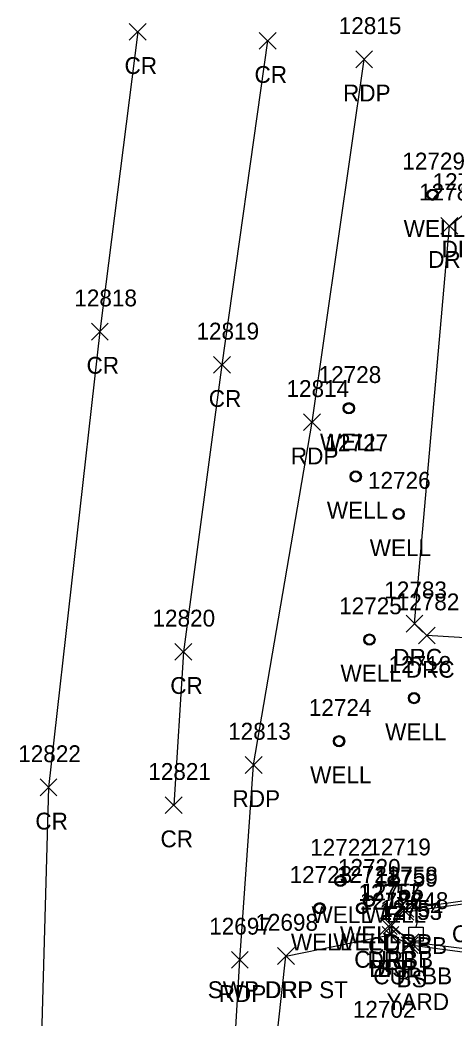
# Model space of a CAD drawing. Extents: x 1769141 to 1770817, y 735471 to 742405.
# Drawn here: x 1770018.6 to 1770070.1, y 741316.5 to 741435 of the extents above; entities that cross this region are included whole.
import ezdxf

# ---------------------------------------------------------------- set-up
doc = ezdxf.new("R2010")
doc.units = 0
for name, color, linetype in [('L_A', 7, 'Continuous'), ('L_I', 7, 'Continuous'), ('L_TIC', 7, 'Continuous'), ('LELB', 7, 'Continuous'), ('P_A', 7, 'Continuous'), ('P_I', 7, 'Continuous'), ('P_TIC', 7, 'Continuous'), ('PET', 7, 'Continuous'), ('PRC', 7, 'Continuous'), ('R_A', 7, 'Continuous'), ('R_I', 7, 'Continuous'), ('R_TIC', 7, 'Continuous'), ('RC', 7, 'Continuous'), ('RDP', 7, 'Continuous'), ('RSW', 7, 'Continuous'), ('U_A', 7, 'Continuous'), ('U_C', 7, 'Continuous'), ('U_I', 7, 'Continuous'), ('ULP', 7, 'Continuous'), ('UWW', 7, 'Continuous')]:
    doc.layers.add(name, color=color, linetype=linetype)

msp = doc.modelspace()

# ---------------------------------------------------------------- linework, layer by layer
at = {"layer": 'L_TIC'}
for points in [[(1770061.58, 741325.38), (1770063.58, 741327.38)], [(1770063.58, 741325.38), (1770061.58, 741327.38)], [(1770063.87, 741324.15), (1770065.87, 741326.15)], [(1770065.87, 741324.15), (1770063.87, 741326.15)]]:
    msp.add_lwpolyline(points, dxfattribs=at)
at = {"layer": 'LELB'}
msp.add_lwpolyline([(1770114.78, 741317.95), (1770086.3, 741322.3), (1770064.87, 741325.15), (1770062.58, 741326.38)], dxfattribs=at)
at = {"layer": 'P_TIC'}
for points in [[(1770031.58, 741432.59), (1770033.58, 741434.59)], [(1770033.58, 741432.59), (1770031.58, 741434.59)], [(1770047, 741431.53), (1770049, 741433.53)], [(1770049, 741431.53), (1770047, 741433.53)], [(1770058.46, 741429.33), (1770060.46, 741431.33)], [(1770060.46, 741429.33), (1770058.46, 741431.33)], [(1770027.07, 741397), (1770029.07, 741399)], [(1770029.07, 741397), (1770027.07, 741399)], [(1770041.58, 741393.06), (1770043.58, 741395.06)], [(1770043.58, 741393.06), (1770041.58, 741395.06)], [(1770052.27, 741386.24), (1770054.27, 741388.24)], [(1770054.27, 741386.24), (1770052.27, 741388.24)], [(1770037, 741358.98), (1770039, 741360.98)], [(1770039, 741358.98), (1770037, 741360.98)], [(1770045.34, 741345.55), (1770047.34, 741347.55)], [(1770047.34, 741345.55), (1770045.34, 741347.55)], [(1770020.98, 741342.88), (1770022.98, 741344.88)], [(1770022.98, 741342.88), (1770020.98, 741344.88)], [(1770035.85, 741340.77), (1770037.85, 741342.77)], [(1770037.85, 741340.77), (1770035.85, 741342.77)], [(1770043.7, 741322.4), (1770045.7, 741324.4)], [(1770045.7, 741322.4), (1770043.7, 741324.4)]]:
    msp.add_lwpolyline(points, dxfattribs=at)
at = {"layer": 'PET'}
msp.add_lwpolyline([(1770060.59, 741195.88), (1770047.65, 741236.89), (1770043.35, 741267.07), (1770042.84, 741291.9), (1770044.7, 741323.4), (1770046.34, 741346.55), (1770053.27, 741387.24), (1770059.46, 741430.33)], dxfattribs=at)
at = {"layer": 'PRC'}
for points in [[(1770032.58, 741433.59), (1770028.07, 741398), (1770021.98, 741343.88), (1770021.04, 741310.16), (1770023.29, 741275.77), (1770029.33, 741237.79), (1770037.81, 741205.4), (1770044.5, 741185.28)], [(1770048, 741432.53), (1770042.58, 741394.06), (1770038, 741359.98), (1770036.85, 741341.77)]]:
    msp.add_lwpolyline(points, dxfattribs=at)
at = {"layer": 'R_TIC'}
for points in [[(1770068.58, 741409.57), (1770070.58, 741411.57)], [(1770070.58, 741409.57), (1770068.58, 741411.57)], [(1770064.44, 741362.33), (1770066.44, 741364.33)], [(1770066.44, 741362.33), (1770064.44, 741364.33)], [(1770065.91, 741360.91), (1770067.91, 741362.91)], [(1770067.91, 741360.91), (1770065.91, 741362.91)], [(1770063.35, 741328.46), (1770065.35, 741330.46)], [(1770065.35, 741328.46), (1770063.35, 741330.46)], [(1770063.36, 741328.1), (1770065.36, 741330.1)], [(1770065.36, 741328.1), (1770063.36, 741330.1)], [(1770061.37, 741326.41), (1770063.37, 741328.41)], [(1770063.37, 741326.41), (1770061.37, 741328.41)], [(1770061.7, 741326.47), (1770063.7, 741328.47)], [(1770063.7, 741326.47), (1770061.7, 741328.47)], [(1770061.58, 741325.38), (1770063.58, 741327.38)], [(1770063.58, 741325.38), (1770061.58, 741327.38)], [(1770063.96, 741324.5), (1770065.96, 741326.5)], [(1770065.96, 741324.5), (1770063.96, 741326.5)], [(1770049.18, 741322.86), (1770051.18, 741324.86)], [(1770051.18, 741322.86), (1770049.18, 741324.86)], [(1770049.18, 741322.86), (1770051.18, 741324.86)], [(1770051.18, 741322.86), (1770049.18, 741324.86)]]:
    msp.add_lwpolyline(points, dxfattribs=at)
at = {"layer": 'RC'}
msp.add_lwpolyline([(1770114.73, 741318.47), (1770086.51, 741322.84), (1770064.96, 741325.5), (1770062.7, 741327.47), (1770064.36, 741329.1), (1770074.29, 741330.5), (1770094.21, 741328.44), (1770115.42, 741325.55), (1770118.61, 741358.67)], dxfattribs=at)
at = {"layer": 'RDP'}
for points in [[(1770094.31, 741365.33), (1770099.54, 741364.65), (1770117.73, 741363.33), (1770115.36, 741330.47), (1770084.76, 741335.36), (1770083.37, 741336.84), (1770085.02, 741360.8), (1770066.91, 741361.91), (1770065.44, 741363.33), (1770069.58, 741410.57), (1770071.17, 741411.81), (1770093.66, 741409.73)], [(1770050.18, 741323.86), (1770062.58, 741326.38), (1770062.37, 741327.41), (1770064.35, 741329.46), (1770074.27, 741330.86), (1770094.16, 741328.75), (1770114.91, 741325.87), (1770118.41, 741359.04), (1770121.56, 741360.23), (1770122.33, 741362.93)]]:
    msp.add_lwpolyline(points, dxfattribs=at)
at = {"layer": 'RSW'}
msp.add_lwpolyline([(1770043.35, 741267.07), (1770046.04, 741266.89), (1770046.9, 741286.26), (1770047.93, 741286.13), (1770048.72, 741289.96), (1770046.62, 741291.82), (1770050.18, 741323.86)], dxfattribs=at)
at = {"layer": 'ULP'}
for p, q in [((1770065.78, 741328.11), (1770065.61, 741327.27)), ((1770064.78, 741325.61), (1770064.78, 741327.27)), ((1770064.78, 741327.27), (1770066.45, 741327.27)), ((1770066.45, 741327.27), (1770066.45, 741325.61)), ((1770066.45, 741325.61), (1770064.78, 741325.61)), ((1770065.36, 741324.77), (1770065.61, 741325.61)), ((1770065.61, 741326.44), (1770065.61, 741326.44))]:
    msp.add_line(p, q, dxfattribs=at)
at = {"layer": 'UWW'}
for centre, radius in [((1770067.59, 741414.25), 0.667), ((1770067.59, 741414.25), 0.625), ((1770067.59, 741414.25), 0.583), ((1770067.59, 741414.25), 0.542), ((1770057.64, 741388.9), 0.667), ((1770057.64, 741388.9), 0.625), ((1770057.64, 741388.9), 0.583), ((1770057.64, 741388.9), 0.542), ((1770058.46, 741380.8), 0.667), ((1770058.46, 741380.8), 0.625), ((1770058.46, 741380.8), 0.583), ((1770058.46, 741380.8), 0.542), ((1770063.56, 741376.34), 0.667), ((1770063.56, 741376.34), 0.625), ((1770063.56, 741376.34), 0.583), ((1770063.56, 741376.34), 0.542), ((1770060.09, 741361.44), 0.667), ((1770060.09, 741361.44), 0.625), ((1770060.09, 741361.44), 0.583), ((1770060.09, 741361.44), 0.542), ((1770065.38, 741354.48), 0.667), ((1770065.38, 741354.48), 0.625), ((1770065.38, 741354.48), 0.583), ((1770065.38, 741354.48), 0.542), ((1770056.48, 741349.37), 0.667), ((1770056.48, 741349.37), 0.625), ((1770056.48, 741349.37), 0.583), ((1770056.48, 741349.37), 0.542), ((1770056.64, 741332.77), 0.667), ((1770056.64, 741332.77), 0.625), ((1770056.64, 741332.77), 0.583), ((1770056.64, 741332.77), 0.542), ((1770062.97, 741332.81), 0.667), ((1770062.97, 741332.81), 0.625), ((1770062.97, 741332.81), 0.583), ((1770062.97, 741332.81), 0.542), ((1770060.03, 741330.38), 0.667), ((1770060.03, 741330.38), 0.625), ((1770060.03, 741330.38), 0.583), ((1770060.03, 741330.38), 0.542), ((1770054.19, 741329.53), 0.667), ((1770054.19, 741329.53), 0.625), ((1770054.19, 741329.53), 0.583), ((1770054.19, 741329.53), 0.542), ((1770059.22, 741329.54), 0.667), ((1770059.22, 741329.54), 0.625), ((1770059.22, 741329.54), 0.583), ((1770059.22, 741329.54), 0.542)]:
    msp.add_circle(centre, radius, dxfattribs=at)

# ---------------------------------------------------------------- texts
at = {"layer": 'L_A'}
for p in [(1770061.02, 741321.38), (1770063.31, 741320.15)]:
    msp.add_text('BS', height=2, dxfattribs=at).set_placement(p)
at = {"layer": 'L_I'}
for s, p in [('12756', (1770058.93, 741329.38)), ('12753', (1770061.28, 741328.15))]:
    msp.add_text(s, height=2, dxfattribs=at).set_placement(p)
at = {"layer": 'P_A'}
for s, p in [('CR', (1770031.01, 741428.59)), ('CR', (1770046.44, 741427.53)), ('RDP', (1770056.95, 741425.33)), ('CR', (1770026.5, 741393)), ('CR', (1770041.01, 741389.06)), ('RDP', (1770050.76, 741382.24)), ('CR', (1770036.44, 741354.98)), ('RDP', (1770043.83, 741341.55)), ('CR', (1770020.42, 741338.88)), ('CR', (1770035.28, 741336.77)), ('RDP', (1770042.19, 741318.4))]:
    msp.add_text(s, height=2, dxfattribs=at).set_placement(p)
at = {"layer": 'P_I'}
for s, p in [('12815', (1770056.44, 741433.33)), ('12818', (1770025.05, 741401)), ('12819', (1770039.55, 741397.06)), ('12814', (1770050.24, 741390.24)), ('12820', (1770034.33, 741362.98)), ('12813', (1770043.31, 741349.55)), ('12822', (1770018.39, 741346.88)), ('12821', (1770033.83, 741344.77)), ('12697', (1770041.06, 741326.4))]:
    msp.add_text(s, height=2, dxfattribs=at).set_placement(p)
at = {"layer": 'R_A'}
for s, p in [('DRC', (1770068.66, 741406.81)), ('DRC', (1770067.06, 741405.57)), ('DRC', (1770062.92, 741358.33)), ('DRC', (1770064.4, 741356.91)), ('CURBB', (1770069.88, 741325.5)), ('CURBB', (1770059.94, 741324.1)), ('DRP', (1770061.84, 741324.46)), ('CURBB', (1770058.28, 741322.47)), ('DRP', (1770059.86, 741322.41)), ('DRP', (1770060.07, 741321.38)), ('CURBB', (1770060.54, 741320.5)), ('SWP DRP ST', (1770040.89, 741318.86)), ('DRP', (1770047.66, 741318.86))]:
    msp.add_text(s, height=2, dxfattribs=at).set_placement(p)
at = {"layer": 'R_I'}
for s, p in [('12785', (1770067.58, 741414.81)), ('12784', (1770065.98, 741413.57)), ('12783', (1770061.85, 741366.33)), ('12782', (1770063.32, 741364.91)), ('12758', (1770060.76, 741332.46)), ('12759', (1770060.76, 741332.1)), ('12757', (1770058.78, 741330.41)), ('12756', (1770058.93, 741329.38)), ('12755', (1770059.11, 741330.47)), ('12754', (1770061.37, 741328.5)), ('12698', (1770046.54, 741326.86)), ('12698', (1770046.54, 741326.86))]:
    msp.add_text(s, height=2, dxfattribs=at).set_placement(p)
at = {"layer": 'U_A'}
for s, p in [('WELL', (1770064.15, 741409.25)), ('WELL', (1770054.21, 741383.9)), ('WELL', (1770055.03, 741375.8)), ('WELL', (1770060.12, 741371.34)), ('WELL', (1770056.65, 741356.44)), ('WELL', (1770061.95, 741349.48)), ('WELL', (1770053.05, 741344.37)), ('WELL', (1770053.21, 741327.77)), ('WELL', (1770059.54, 741327.81)), ('WELL', (1770056.59, 741325.38)), ('WELL', (1770050.76, 741324.53)), ('WELL', (1770055.79, 741324.54)), ('LI', (1770064.72, 741321.44))]:
    msp.add_text(s, height=2, dxfattribs=at).set_placement(p)
at = {"layer": 'U_C'}
msp.add_text('YARD', height=2, dxfattribs=at).set_placement((1770062.11, 741317.44))
at = {"layer": 'U_I'}
for s, p in [('12729', (1770063.99, 741417.25)), ('12728', (1770054.05, 741391.9)), ('12727', (1770054.87, 741383.8)), ('12726', (1770059.91, 741379.34)), ('12725', (1770056.49, 741364.44)), ('12718', (1770062.36, 741357.48)), ('12724', (1770052.89, 741352.37)), ('12722', (1770053.05, 741335.77)), ('12719', (1770059.94, 741335.81)), ('12720', (1770056.35, 741333.38)), ('12723', (1770050.6, 741332.53)), ('12721', (1770056.2, 741332.54)), ('12748', (1770062.02, 741329.44)), ('12702', (1770058.11, 741316.53))]:
    msp.add_text(s, height=2, dxfattribs=at).set_placement(p)

doc.saveas('drawing.dxf')
